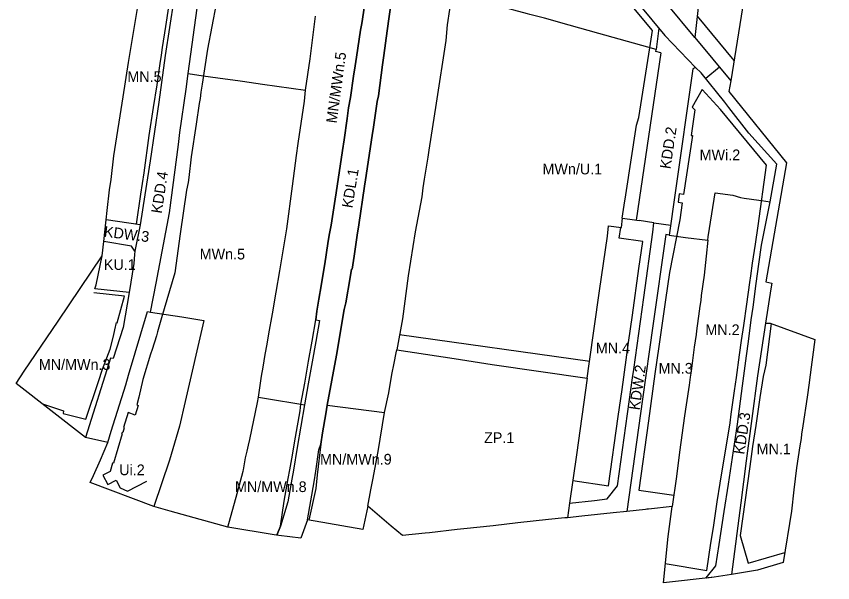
# Model space of a CAD drawing. Extents: x 7420394 to 7421866, y 5549214 to 5549912.
# Drawn here: x 7420872.2 to 7421253.2, y 5549213.7 to 5549478.2 of the extents above; entities that cross this region are included whole.
import ezdxf

# ---------------------------------------------------------------- set-up
doc = ezdxf.new("R2010")
doc.units = 0
for name, color, linetype in [('linie_rozgraniczajace', 7, 'Continuous'), ('linie_zabudowy_nieprzekraczalne', 7, 'Continuous'), ('linie_zabudowy_obowiazujace', 7, 'Continuous'), ('oznaczenia_przeznaczen', 7, 'Continuous')]:
    doc.layers.add(name, color=color, linetype=linetype)

msp = doc.modelspace()

# ---------------------------------------------------------------- linework, layer by layer
at = {"layer": 'linie_rozgraniczajace'}
for p, q in [((7421189.23, 5549454.25), (7421174.87, 5549469.32)), ((7421200.32, 5549454.46), (7421193.99, 5549449.18)), ((7421169.71, 5549381.84), (7421177.57, 5549380.73)), ((7421017.25, 5549296.65), (7421044.07, 5549293.14))]:
    msp.add_line(p, q, dxfattribs=at)
for points in [[(7421253.18, 5549679.64), (7421243.94, 5549685.34), (7421221.51, 5549698.23), (7421215.2, 5549654.89), (7421212.44, 5549634.92), (7421211.17, 5549624.99), (7421209.9, 5549615.08), (7421208.44, 5549605.15), (7421207.02, 5549595.35), (7421203.92, 5549575.53), (7421200.58, 5549552.73), (7421200.15, 5549548.95), (7421198.21, 5549536.85), (7421198, 5549533), (7421197.27, 5549529.03), (7421195.53, 5549517.1), (7421194.97, 5549512.92), (7421193.47, 5549502.81), (7421191.92, 5549492.29), (7421190.39, 5549482.29), (7421188.8, 5549468.35), (7421205.59, 5549448.1)], [(7420914.87, 5549279.19), (7420916.51, 5549284.52), (7420923.22, 5549306.17), (7420924.6, 5549310.62), (7420933.35, 5549340.3), (7420934.85, 5549340.07), (7420937.47, 5549353.53), (7420943.65, 5549386.5), (7420947.81, 5549418.43), (7420948.52, 5549423.89), (7420951.44, 5549444.25), (7420952.43, 5549451.44), (7420976.48, 5549626.81)], [(7420932.59, 5549507.57), (7420945.52, 5549505.71), (7420948.17, 5549502.31), (7420945.71, 5549486.23), (7420941.62, 5549459.84), (7420938.63, 5549438.07), (7420934.66, 5549410.7), (7420932.11, 5549394.85), (7420929.94, 5549380.88), (7420914.09, 5549383.12)], [(7421008.02, 5549243.05), (7421011.12, 5549260.88), (7421011.94, 5549265.82), (7421013.44, 5549275.75), (7421014.23, 5549278.46), (7421015.06, 5549283.75), (7421016.62, 5549292.59), (7421017.25, 5549296.65), (7421021.68, 5549319.99), (7421025.24, 5549341.24), (7421025.91, 5549344.44), (7421027.95, 5549356.26), (7421028.59, 5549360.19), (7421028.88, 5549360.14), (7421029.87, 5549366.24), (7421031.23, 5549375.98), (7421032, 5549380.83), (7421034.75, 5549398.95), (7421035.1, 5549401.83), (7421038.26, 5549422.61), (7421038.9, 5549426.38), (7421040.65, 5549438.36), (7421041.15, 5549441.07), (7421043.06, 5549455.59), (7421043.7, 5549459.94), (7421045.31, 5549471.48), (7421046.19, 5549478.12), (7421049.35, 5549500.24)], [(7421036.41, 5549494.58), (7421033.39, 5549474.87), (7421032.86, 5549471.8), (7421030.91, 5549459.12), (7421030.38, 5549455.16), (7421029.61, 5549450.29), (7421028.08, 5549440.37), (7421027.28, 5549435.43), (7421026.62, 5549430.48), (7421025.2, 5549420.57), (7421024.43, 5549415.54), (7421021.43, 5549395.76), (7421021.03, 5549392.79), (7421019.13, 5549380.75), (7421018.19, 5549375.98), (7421017.6, 5549372.09), (7421016.13, 5549362.6), (7421015.04, 5549356.17), (7421014.4, 5549352.28), (7421013.37, 5549346.13), (7421012.41, 5549340.45), (7421011.9, 5549336.45), (7421013.65, 5549336.09), (7421011.9, 5549326.31), (7421010.23, 5549316.86), (7421008.41, 5549306.66), (7421006.65, 5549296.77), (7421003.28, 5549276.93), (7421001.5, 5549266.2), (7421000.82, 5549262.06), (7420998.86, 5549251.48), (7420995.49, 5549240.07), (7420993.71, 5549235.89)], [(7421188.8, 5549468.35), (7421175.96, 5549483.85), (7421169, 5549491.74)], [(7421212.13, 5549489.24), (7421205.59, 5549448.1), (7421204.68, 5549443.03), (7421231.64, 5549409.78), (7421221.91, 5549354.15), (7421224.75, 5549353.64), (7421224.39, 5549351.02), (7421221.84, 5549334.97), (7421224.01, 5549334.92), (7421244.86, 5549327.36), (7421242.41, 5549308.51), (7421242.22, 5549307.12), (7421241.28, 5549300.29), (7421239.19, 5549286.96), (7421238.69, 5549283.09), (7421238.43, 5549281.08), (7421237.86, 5549277.67), (7421236.27, 5549267.37), (7421235.11, 5549257.07), (7421234, 5549247.09), (7421230.07, 5549223.15), (7421218.11, 5549219.51), (7421205.92, 5549217.61), (7421197.83, 5549216.24), (7421174.16, 5549213.73), (7421176.4, 5549235.36), (7421178.34, 5549249.37), (7421167.16, 5549248.13), (7421166.41, 5549248.04), (7421165.85, 5549247.98), (7421157.16, 5549247.02), (7421150.71, 5549246.3), (7421136.07, 5549244.74), (7421129.42, 5549244.08), (7421128.25, 5549243.97), (7421120.56, 5549243.16), (7421106.23, 5549241.63), (7421094.69, 5549240.28), (7421081.06, 5549238.83), (7421077.88, 5549238.49), (7421065.03, 5549237.08), (7421063.04, 5549236.87), (7421052.35, 5549235.74), (7421047.11, 5549240.15), (7421036.26, 5549249.4), (7421033.93, 5549238.62), (7421008.02, 5549243.05), (7421005.04, 5549234.52), (7420994.7, 5549235.71), (7420992.52, 5549236.1), (7420970.85, 5549239.67), (7420946.81, 5549246.4), (7420943.93, 5549247.2), (7420936.35, 5549249.33), (7420906.67, 5549260.58), (7420908.12, 5549263.73), (7420911.49, 5549271.05), (7420914.87, 5549279.19), (7420904.49, 5549281.56), (7420872.18, 5549306.81), (7420875.88, 5549312.49), (7420891.65, 5549335.85), (7420912.29, 5549366.43), (7420912.96, 5549373.09), (7420914.09, 5549383.12), (7420914.65, 5549387.49), (7420915.66, 5549397.24), (7420916.38, 5549402.07), (7420917.71, 5549413.05), (7420922, 5549440.55), (7420924.61, 5549456.71), (7420925.5, 5549462.27), (7420929.89, 5549488.62)], [(7421172.96, 5549461.1), (7421170.68, 5549461.76), (7421170.8, 5549462.68), (7421166.96, 5549463.75), (7421144, 5549470.2), (7421130.25, 5549474.05), (7421118.68, 5549477.3), (7421111.82, 5549479.12), (7421110.7, 5549479.42), (7421104.37, 5549481.06), (7421075.46, 5549488.67), (7421073.27, 5549474.2), (7421072.61, 5549466.85), (7421068.08, 5549437.61), (7421064.7, 5549415.71), (7421064.2, 5549412.48), (7421062.59, 5549402.09), (7421061.97, 5549398.09), (7421061.36, 5549393.93), (7421058.34, 5549377.64), (7421055.04, 5549357.09), (7421052.39, 5549336.92), (7421049.74, 5549322.52)], [(7421162.73, 5549483.85), (7421174.87, 5549469.32)], [(7420970.85, 5549239.67), (7420975.32, 5549255.31), (7420978.03, 5549265.86), (7420978.13, 5549266.44), (7420979.15, 5549271.96), (7420979.88, 5549275.09), (7420980.53, 5549277.92), (7420981.14, 5549280.52), (7420984.74, 5549297.9), (7420985.22, 5549300.4), (7420986.61, 5549310.2), (7420987.31, 5549314.31), (7420988.34, 5549320.27), (7420989.28, 5549325.19), (7420990.09, 5549329.9), (7420991.71, 5549339.35), (7420993.42, 5549349.43), (7420995.12, 5549359.42), (7420998.46, 5549379.01), (7421001.05, 5549398.84), (7421002.98, 5549413.23), (7421003.65, 5549418.77), (7421006.68, 5549438.53), (7421007.11, 5549443.75), (7421009.31, 5549458.32), (7421011.82, 5549478.31)], [(7421172.01, 5549472.73), (7421170.8, 5549462.68)], [(7421172.96, 5549461.1), (7421161.41, 5549383.07)], [(7421197.83, 5549216.24), (7421194.4, 5549215.88), (7421194.18, 5549216.04), (7421198.63, 5549221.56), (7421198.63, 5549221.57), (7421200.14, 5549231.59), (7421202.5, 5549246.9), (7421204.54, 5549259.71), (7421208.69, 5549287.83), (7421211.08, 5549305.73), (7421212.95, 5549319.7), (7421213.83, 5549326.33), (7421215.2, 5549336.52), (7421216.06, 5549342.34), (7421217.43, 5549353.39), (7421218.76, 5549362.44), (7421220.03, 5549371.34), (7421224.07, 5549391.6), (7421227.16, 5549409.18), (7421213.98, 5549423.64), (7421204.72, 5549435.66), (7421202.81, 5549438.07), (7421191.87, 5549451.85), (7421189.23, 5549454.25), (7421187.92, 5549453.69), (7421179.7, 5549395.74), (7421176.91, 5549376.08), (7421175.26, 5549376.31), (7421169.3, 5549333.66), (7421164.49, 5549299.36), (7421157.16, 5549247.02)], [(7420952.43, 5549451.44), (7420959.37, 5549450.47), (7420966.26, 5549449.5), (7420976.65, 5549448.04), (7420977.68, 5549447.89), (7420987.04, 5549446.58), (7421007.11, 5549443.75)], [(7421176.91, 5549376.08), (7421184.52, 5549374.88), (7421194.85, 5549373.63), (7421195.11, 5549375.22), (7421197.93, 5549392.89), (7421198.38, 5549395.79), (7421206.59, 5549394.63), (7421210.1, 5549393.53), (7421211.86, 5549393.29), (7421218.79, 5549392.37), (7421220.01, 5549392.2), (7421224.07, 5549391.6)], [(7421138.66, 5549309.31), (7421139.6, 5549315.96), (7421144.43, 5549350.04), (7421148.04, 5549375.52), (7421148.49, 5549380.38), (7421154.59, 5549379.52), (7421155.16, 5549383.98), (7421160.66, 5549383.18), (7421162.94, 5549382.84)], [(7420929.94, 5549380.88), (7420927.56, 5549368.59), (7420927.41, 5549367.05), (7420926.98, 5549362.72), (7420924.91, 5549349.29), (7420908.86, 5549351), (7420909.5, 5549352.84), (7420912.29, 5549366.43)], [(7421130.37, 5549250.86), (7421142.03, 5549252.17), (7421148, 5549252.84), (7421152.8, 5549259), (7421159.82, 5549309.36), (7421160.37, 5549313.27), (7421165.06, 5549346.98), (7421169.3, 5549377.36), (7421169.71, 5549381.84), (7421162.94, 5549382.84)], [(7420927.56, 5549368.59), (7420925.93, 5549370.89), (7420912.96, 5549373.09)], [(7421194.85, 5549373.63), (7421194.07, 5549366.16), (7421193.13, 5549357.27), (7421191.88, 5549347.8), (7421191.58, 5549345.47), (7421191.23, 5549342.83), (7421190.93, 5549340.56), (7421189.67, 5549331.35), (7421189.43, 5549329.67), (7421188.61, 5549323.69), (7421187.08, 5549312.53), (7421186.69, 5549309.73), (7421186.13, 5549305.92), (7421184.76, 5549296.82), (7421183.98, 5549291.58), (7421181.69, 5549274.61), (7421180.25, 5549263.26), (7421178.34, 5549249.37), (7421178.34, 5549249.37)], [(7420924.91, 5549349.29), (7420921.99, 5549332.9), (7420917.35, 5549318.38), (7420916.18, 5549318.65), (7420904.49, 5549281.56)], [(7420934.85, 5549340.07), (7420949.43, 5549337.8), (7420959.69, 5549336.21), (7420950.92, 5549298.29), (7420948.27, 5549286.86), (7420943.66, 5549270.99), (7420936.35, 5549249.33)], [(7421221.84, 5549334.97), (7421218.17, 5549310.38), (7421215.48, 5549290.46), (7421212.83, 5549270.7), (7421210.33, 5549250.95), (7421205.92, 5549217.61)], [(7421036.26, 5549249.4), (7421037.7, 5549257.02), (7421038.58, 5549261.74), (7421041.04, 5549274.97), (7421044.07, 5549293.14), (7421046.03, 5549302.37), (7421047.45, 5549310.9), (7421048.58, 5549316.29), (7421049.46, 5549321.02), (7421049.74, 5549322.52), (7421076.46, 5549318.36), (7421094.25, 5549315.59), (7421138.66, 5549309.31), (7421133.56, 5549273.36), (7421130.37, 5549250.86), (7421129.42, 5549244.08)], [(7420985.22, 5549300.4), (7420989.9, 5549299.61), (7421005.02, 5549297.04), (7421006.65, 5549296.77)]]:
    msp.add_lwpolyline(points, dxfattribs=at)
at = {"layer": 'linie_zabudowy_nieprzekraczalne'}
for p, q in [((7420922.61, 5549347.52), (7420908.42, 5549349.04)), ((7421051.04, 5549329.56), (7421139.78, 5549317.25)), ((7421131.88, 5549261.49), (7421148.56, 5549259.03)), ((7421162.69, 5549256.94), (7421179.05, 5549254.53)), ((7421175.08, 5549222.62), (7421194.43, 5549219.43))]:
    msp.add_line(p, q, dxfattribs=at)
for points in [[(7421155, 5549384), (7421155.9, 5549389.95), (7421156.63, 5549394.8), (7421161.64, 5549427.31), (7421162.73, 5549430.99), (7421167.78, 5549463.52), (7421169.03, 5549471.53), (7421146.17, 5549499.17), (7421135.63, 5549511.93), (7421127.02, 5549522.33), (7421118.93, 5549531.76), (7421115.16, 5549536.16)], [(7421189.93, 5549478.21), (7421207.09, 5549457.52)], [(7421222.24, 5549408.76), (7421200.84, 5549434.65), (7421192.25, 5549444.1)], [(7421209.95, 5549235.76), (7421213.67, 5549222.92), (7421230.85, 5549227.9)]]:
    msp.add_lwpolyline(points, dxfattribs=at)
at = {"layer": 'linie_zabudowy_obowiazujace'}
for points in [[(7420928.34, 5549381.11), (7420930.35, 5549395.14), (7420931.82, 5549405.18), (7420934.24, 5549422.49), (7420936.14, 5549435.56), (7420937.84, 5549446.18), (7420939.34, 5549456.2), (7420939.87, 5549460.1), (7420940.41, 5549463.63), (7420942, 5549473.53), (7420943.36, 5549482.58), (7420946.54, 5549504.4)], [(7421049.35, 5549500.24), (7421046.19, 5549478.12), (7421045.31, 5549471.48), (7421043.7, 5549459.94), (7421043.06, 5549455.59), (7421041.15, 5549441.07), (7421040.65, 5549438.36), (7421038.9, 5549426.38), (7421038.26, 5549422.61), (7421035.1, 5549401.83), (7421034.75, 5549398.95), (7421032, 5549380.83), (7421031.23, 5549375.98), (7421029.87, 5549366.24), (7421028.88, 5549360.14), (7421028.59, 5549360.19), (7421027.95, 5549356.26), (7421025.91, 5549344.44), (7421025.24, 5549341.24), (7421021.68, 5549319.99), (7421017.25, 5549296.65), (7421016.62, 5549292.59), (7421015.06, 5549283.75), (7421014.23, 5549278.46), (7421012.59, 5549264.07), (7421011.95, 5549257.68), (7421008.77, 5549242.92)], [(7420993.71, 5549235.89), (7420995.49, 5549240.07), (7420997.26, 5549251.75), (7420999.11, 5549262.39), (7420999.82, 5549266.48), (7421001.03, 5549273.33), (7421001.63, 5549277.24), (7421002.42, 5549281.75), (7421004.63, 5549293.93), (7421005.02, 5549297.04), (7421006.78, 5549306.93), (7421008.58, 5549317.11), (7421010.21, 5549326.59), (7421011.9, 5549336.45), (7421012.41, 5549340.45), (7421013.37, 5549346.13), (7421014.4, 5549352.28), (7421015.04, 5549356.17), (7421016.13, 5549362.6), (7421017.6, 5549372.09), (7421018.19, 5549375.98), (7421019.13, 5549380.75), (7421021.03, 5549392.79), (7421021.43, 5549395.76), (7421024.43, 5549415.54), (7421025.2, 5549420.57), (7421026.62, 5549430.48), (7421027.28, 5549435.43), (7421028.08, 5549440.37), (7421029.61, 5549450.29), (7421030.38, 5549455.16), (7421030.91, 5549459.12), (7421032.86, 5549471.8), (7421033.39, 5549474.87), (7421036.41, 5549494.58)], [(7420965.5, 5549484.12), (7420961.4, 5549462.83), (7420958.87, 5549446.49), (7420958.32, 5549442.73), (7420957.92, 5549439.91), (7420957.56, 5549437.48), (7420956.17, 5549427.84), (7420953.78, 5549412.59), (7420952.72, 5549402.93), (7420952.37, 5549400.66), (7420951.67, 5549397.04), (7420948.68, 5549376.67), (7420946.17, 5549358.37), (7420940, 5549337.39), (7420938.11, 5549330.82), (7420937.58, 5549329.08), (7420935.65, 5549322.68), (7420934.84, 5549320.52), (7420931.24, 5549308.62), (7420929.33, 5549300.32), (7420928.35, 5549296.73), (7420929.09, 5549296.5), (7420927.71, 5549292), (7420924.34, 5549293.14), (7420922.19, 5549286.16), (7420922.46, 5549286.06), (7420921.84, 5549283.89), (7420921.51, 5549283.93), (7420921.31, 5549283.31), (7420921.58, 5549283.22), (7420917.54, 5549269.54), (7420917.02, 5549269.6), (7420915.91, 5549265.65), (7420912.49, 5549263.94), (7420914.9, 5549259.58), (7420918.84, 5549261.6), (7420920.65, 5549257.97), (7420924.09, 5549256.5), (7420933.02, 5549261.11)], [(7421192.25, 5549444.1), (7421187.57, 5549435.74), (7421188.89, 5549434.59), (7421187.07, 5549422.63), (7421187.77, 5549422.53), (7421183.57, 5549394.97), (7421181.6, 5549395.27), (7421181.02, 5549391.44), (7421183, 5549391.14), (7421181.79, 5549383.18), (7421176.98, 5549358.58), (7421175.19, 5549345.85), (7421171.97, 5549324.01), (7421170.16, 5549311.2), (7421167.23, 5549289.35), (7421162.69, 5549256.94)], [(7421194.43, 5549219.43), (7421196.31, 5549232.18), (7421197.54, 5549239.55), (7421199.34, 5549251.53), (7421200.64, 5549260.28), (7421205.31, 5549288.34), (7421205.84, 5549292.37), (7421207.38, 5549303.38), (7421208.25, 5549309.58), (7421209.66, 5549320.19), (7421210.63, 5549326.77), (7421211.66, 5549333.79), (7421213.13, 5549343.87), (7421214.54, 5549353.88), (7421215.05, 5549356.99), (7421215.83, 5549362.88), (7421217.13, 5549371.79), (7421218.41, 5549380.31), (7421222.24, 5549408.76)], [(7421148.56, 5549259.03), (7421153.14, 5549291.32), (7421154.92, 5549304), (7421157.93, 5549325.92), (7421159.71, 5549338.59), (7421162.76, 5549360.41), (7421164.57, 5549373.06), (7421153.58, 5549374.62), (7421154.33, 5549379.56)], [(7420884.35, 5549297.3), (7420894.24, 5549293.91), (7420894.07, 5549292.76), (7420904.68, 5549290.02), (7420910.46, 5549307.69), (7420912.36, 5549313.4), (7420916.02, 5549322.75), (7420917.52, 5549328.84), (7420918.22, 5549331.76), (7420919, 5549335.16), (7420919.29, 5549335.08), (7420922.61, 5549347.52)], [(7421224.5, 5549334.74), (7421221.97, 5549315.3), (7421220.7, 5549310), (7421219.15, 5549300.26), (7421217.38, 5549287.13), (7421215.78, 5549277.26), (7421214.57, 5549268.06), (7421209.95, 5549235.76)]]:
    msp.add_lwpolyline(points, dxfattribs=at)

# ---------------------------------------------------------------- texts
at = {"layer": 'oznaczenia_przeznaczen'}
for s, rotation, p in [('MN/MWn.5', 82.2117, (7421021.66, 5549428.06)), ('KDD.2', 81.326, (7421177.43, 5549406.69)), ('KDL.1', 80.5131, (7421028.97, 5549388.43)), ('KDD.4', 81.3797, (7420940.04, 5549385.91)), ('KDW.3', 352.9035, (7420912.87, 5549375.34)), ('KDW.2', 81.843, (7421163.04, 5549294.08)), ('KDD.3', 81.3278, (7421211.9, 5549273.39))]:
    msp.add_text(s, height=5, rotation=rotation, dxfattribs=at).set_placement(p)
for s, p in [('MN.5', (7420923.99, 5549447.56)), ('MWi.2', (7421191.08, 5549411.02)), ('MWn/U.1', (7421117.74, 5549404.4)), ('MWn.5', (7420957.75, 5549364.67)), ('KU.1', (7420913.04, 5549359.79)), ('MN.2', (7421193.77, 5549329.35)), ('MN.4', (7421142.64, 5549320.79)), ('MN/MWn.3', (7420882.68, 5549313.11)), ('MN.3', (7421171.9, 5549311.36)), ('ZP.1', (7421090.48, 5549278.95)), ('MN.1', (7421217.68, 5549273.7)), ('MN/MWn.9', (7421013.93, 5549268.88)), ('Ui.2', (7420920.22, 5549263.93)), ('MN/MWn.8', (7420974.23, 5549256.05))]:
    msp.add_text(s, height=5, dxfattribs=at).set_placement(p)

doc.saveas('drawing.dxf')
